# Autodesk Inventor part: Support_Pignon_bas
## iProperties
Created: 2008-12
Part Number: Support_Pignon_bas
Document SubType Name: Sheet Metal
Designer: LAIVIER CYRIL
Author: LAIVIER CYRIL
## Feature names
1. Perçage1 [Hole]
2. Perçage2 [Hole]
3. Chanfrein de coin1
4. Chanfrein de coin2
5. Plaque1
6. Pli1
